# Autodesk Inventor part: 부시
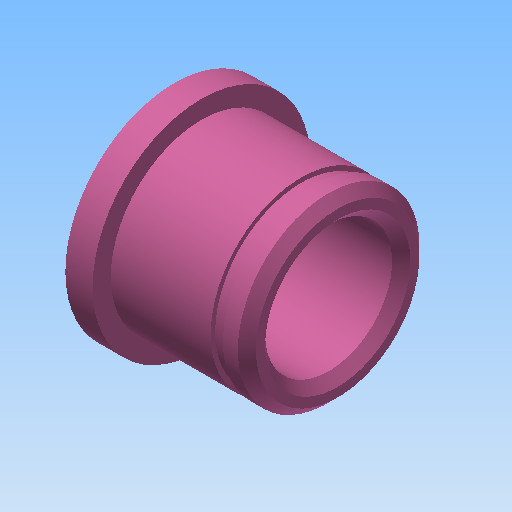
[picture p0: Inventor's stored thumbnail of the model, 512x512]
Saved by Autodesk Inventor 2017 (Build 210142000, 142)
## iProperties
Created: 2019-01
Part Number: 부시
Material: 강철, 연강
Document SubType Name: Modeling
Designer: mduedu
Density: 7.86 g/cm^3
Appearance: 분홍색
Mass: 25.1828 g
Surface Area: 25.5171 cm^2
Volume: 3.20391 cm^3
Author: mduedu
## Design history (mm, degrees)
sketch "스케치1"
  geometry: L1 (0, 0)-(3, 0); L2 (3, 0)-(3, 12); L3 (3, 12)-(0, 12); L4 (0, 12)-(0, 0); L5 (3, 0)-(18, 0); L6 (18, 0)-(18, 10); L7 (18, 10)-(3, 10); L8 (3, 10)-(3, 0)
  constraints: 16 end point, 4 parallel, 2 horizontal, 2 perpendicular
  dimensions: "d0" = 18 distance between parallel lines of L6 L4; "d2" = 3 distance of L2.end L3.end; "d3" = 24 diameter of L3 L1; "d4" = 20 diameter of L7 L5
revolve "회전1" sketch "스케치1" stored, may be unused: angle "d5" = 90 deg
sketch "스케치2"
  geometry: C1 r 7 at (0, 0); 1 further point
  constraints: 1 centre point, 1 coincident
  dimensions: "d6" = 14 diameter of C1
extrude "돌출1" cut sketch "스케치2" stored distance "d7" = 10; taper "d8" = 0 deg
chamfer "모따기1" distance "d9" = 1; stored, may be unused: second distance "d10" = 2, angle "d11" = 45 deg
node "작업 평면1"
sketch "스케치3"
  geometry: C1 r 9.5 at (0, 0); C2 r 10 at (0, 0) reference; 1 further point
  constraints: 1 centre point, 1 coincident
  dimensions: "d13" = 19 diameter of C1
extrude "돌출2" cut sketch "스케치3" distance "d14" = 1.35; taper "d15" = 0 deg
node "솔리드1"
other parameters: "d12" = 11
